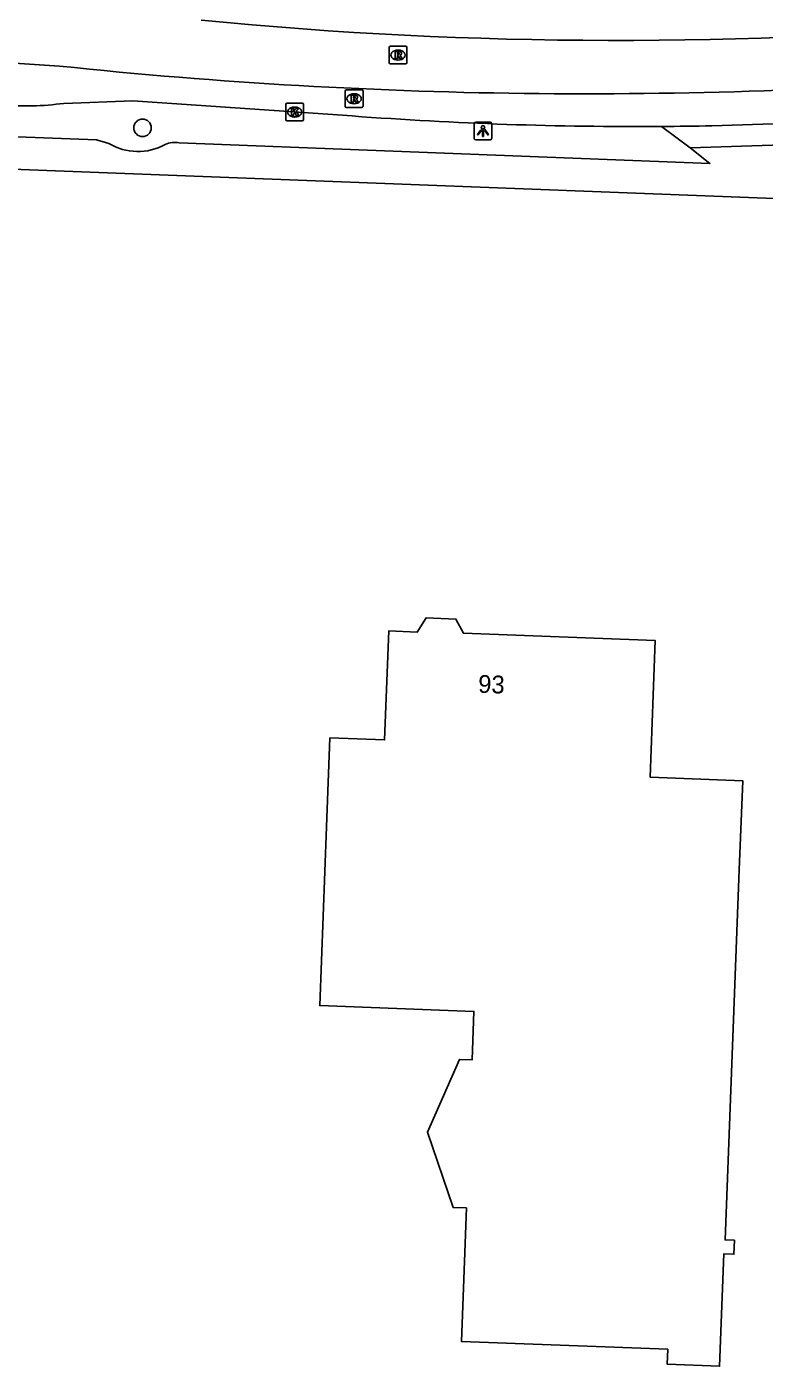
# Model space of a CAD drawing. Extents: x 161772 to 163123, y 383092 to 383917.
# Drawn here: x 162162.8 to 162204.2, y 383545.7 to 383620.9 of the extents above; entities that cross this region are included whole.
import ezdxf

# ---------------------------------------------------------------- set-up
doc = ezdxf.new("R2010")
doc.units = 0
for name, color, linetype in [('IMGEO_Boom', 7, 'Continuous'), ('IMGEO_Kolk', 7, 'Continuous'), ('IMGEO_Lichtpunt', 7, 'Continuous'), ('IMGEO_Pand', 7, 'Continuous'), ('IMGEO_Pand_nummerreeks', 7, 'Continuous'), ('IMGEO_Rijbaan_lokaal_gesloten', 7, 'Continuous'), ('IMGEO_Rioolput', 7, 'Continuous'), ('IMGEO_Voetpad_open', 7, 'Continuous')]:
    doc.layers.add(name, color=color, linetype=linetype)

msp = doc.modelspace()

# ---------------------------------------------------------------- linework, layer by layer
at = {"layer": 'IMGEO_Boom'}
msp.add_circle((162169.309, 383615.222), 0.489, dxfattribs=at)
at = {"layer": 'IMGEO_Kolk'}
for p, q in [((162177.353, 383615.684), (162177.353, 383616.536)), ((162177.428, 383616.61), (162178.28, 383616.61)), ((162177.841, 383616.39), (162177.866, 383616.39)), ((162178.354, 383616.536), (162178.354, 383615.684)), ((162178.28, 383615.61), (162177.428, 383615.61)), ((162177.864, 383615.83), (162177.839, 383615.83))]:
    msp.add_line(p, q, dxfattribs=at)
for points in [[(162177.353, 383615.684), (162177.353, 383616.536)], [(162177.428, 383616.61), (162178.28, 383616.61)], [(162177.674, 383616.31), (162177.797, 383616.31), (162177.797, 383616.159), (162177.927, 383616.31), (162178.091, 383616.31), (162177.945, 383616.159), (162178.098, 383615.91), (162177.946, 383615.91), (162177.861, 383616.074), (162177.797, 383616.007), (162177.797, 383615.91), (162177.674, 383615.91), (162177.674, 383616.31)], [(162178.354, 383616.536), (162178.354, 383615.684)], [(162178.28, 383615.61), (162177.428, 383615.61)]]:
    msp.add_lwpolyline(points, dxfattribs=at)
for centre, start, end in [((162177.43, 383616.534), 91.55205, 178.44795), ((162177.43, 383616.534), 91.55205, 178.44795), ((162178.278, 383616.534), 1.55205, 88.44795), ((162178.278, 383616.534), 1.55205, 88.44795), ((162177.43, 383615.686), 181.55205, 268.44795), ((162177.43, 383615.686), 181.55205, 268.44795), ((162178.278, 383615.686), 271.55205, 358.44795), ((162178.278, 383615.686), 271.55205, 358.44795)]:
    msp.add_arc(centre, 0.0765, start, end, dxfattribs=at)
for centre, major_axis, ratio, start_param, end_param in [((162177.84, 383616.11), (-0.387, 0.002), 0.722429, 4.712389, 7.853982), ((162177.865, 383616.11), (-0.39, 0.002), 0.717154, 1.570796, 4.712389)]:
    msp.add_ellipse(centre, major_axis=major_axis, ratio=ratio, start_param=start_param, end_param=end_param, dxfattribs=at)
at = {"layer": 'IMGEO_Lichtpunt'}
for p, q in [((162187.933, 383615.449), (162187.933, 383614.642)), ((162187.933, 383615.449), (162187.933, 383614.642)), ((162188.835, 383615.544), (162188.027, 383615.544)), ((162188.835, 383615.544), (162188.027, 383615.544)), ((162188.929, 383614.642), (162188.929, 383615.449)), ((162188.929, 383614.642), (162188.929, 383615.449)), ((162188.027, 383614.548), (162188.835, 383614.548)), ((162188.027, 383614.548), (162188.835, 383614.548))]:
    msp.add_line(p, q, dxfattribs=at)
for points in [[(162188.307, 383615.113), (162188.346, 383615.085), (162188.158, 383614.823), (162188.12, 383614.85), (162188.307, 383615.113)], [(162188.409, 383615.065), (162188.456, 383615.065), (162188.456, 383614.743), (162188.409, 383614.743), (162188.409, 383615.065)], [(162188.519, 383615.085), (162188.557, 383615.112), (162188.744, 383614.85), (162188.705, 383614.822), (162188.519, 383615.085)]]:
    msp.add_lwpolyline(points, dxfattribs=at)
msp.add_circle((162188.432, 383615.247), 0.0994, dxfattribs=at)
for centre, start, end in [((162188.027, 383615.449), 90, 180), ((162188.027, 383615.449), 90, 180), ((162188.835, 383615.449), 0, 90), ((162188.835, 383615.449), 0, 90), ((162188.027, 383614.642), 180, 270), ((162188.027, 383614.642), 180, 270), ((162188.835, 383614.642), 270, 0), ((162188.835, 383614.642), 270, 360)]:
    msp.add_arc(centre, 0.0946, start, end, dxfattribs=at)
at = {"layer": 'IMGEO_Pand'}
msp.add_lwpolyline([(162202.831, 383573.564), (162203.022, 383578.56), (162197.817, 383578.759), (162198.111, 383586.426), (162187.332, 383586.839), (162186.911, 383587.638), (162185.238, 383587.702), (162184.738, 383586.907), (162183.142, 383586.968), (162182.907, 383580.848), (162179.835, 383580.965), (162179.644, 383575.969), (162179.26, 383565.936), (162187.929, 383565.604), (162187.825, 383562.883), (162187.106, 383562.91), (162185.309, 383558.829), (162186.765, 383554.596), (162187.506, 383554.567), (162187.219, 383547.073), (162198.814, 383546.629), (162198.782, 383545.794), (162201.728, 383545.681), (162201.969, 383551.993), (162202.528, 383551.972), (162202.558, 383552.752), (162202.034, 383552.772), (162202.831, 383573.564)], dxfattribs=at)
at = {"layer": 'IMGEO_Rijbaan_lokaal_gesloten'}
for points in [[(162161.548, 383618.884), (162164.644, 383618.69)], [(162181.085, 383615.888), (162168.773, 383616.735), (162164.893, 383616.595)], [(162212.842, 383615.851), (162207.025, 383615.525), (162201.283, 383615.334)]]:
    msp.add_lwpolyline(points, dxfattribs=at)
for centre, radius, start, end in [((162196.013, 383862.02), 241.892, 264.44839, 275.296), ((162194.259, 383899.063), 281.932, 263.9704, 274.94108), ((162162.72, 383632.69), 16.241, 265.15652, 277.68828), ((162197.055, 383829.7), 214.407, 265.72839, 270.37491), ((162196.971, 383836.713), 221.421, 270.38484, 271.11592)]:
    msp.add_arc(centre, radius, start, end, dxfattribs=at)
at = {"layer": 'IMGEO_Rioolput'}
for p, q in [((162183.237, 383619.807), (162184.089, 383619.807)), ((162183.162, 383618.881), (162183.162, 383619.733)), ((162183.65, 383619.587), (162183.675, 383619.587)), ((162184.163, 383619.733), (162184.163, 383618.881)), ((162184.089, 383618.807), (162183.237, 383618.807)), ((162183.673, 383619.027), (162183.648, 383619.027)), ((162180.693, 383616.429), (162180.693, 383617.281)), ((162180.768, 383617.355), (162181.62, 383617.355)), ((162181.181, 383617.135), (162181.206, 383617.135)), ((162181.694, 383617.281), (162181.694, 383616.429)), ((162181.62, 383616.355), (162180.768, 383616.355)), ((162181.204, 383616.575), (162181.179, 383616.575))]:
    msp.add_line(p, q, dxfattribs=at)
for points in [[(162183.237, 383619.807), (162184.089, 383619.807)], [(162183.162, 383618.881), (162183.162, 383619.733)], [(162183.751, 383619.505), (162183.499, 383619.507), (162183.499, 383619.107)], [(162183.499, 383619.107), (162183.623, 383619.107), (162183.623, 383619.269), (162183.634, 383619.269)], [(162183.677, 383619.426), (162183.623, 383619.426), (162183.623, 383619.345)], [(162183.623, 383619.345), (162183.675, 383619.345)], [(162183.681, 383619.24), (162183.752, 383619.107), (162183.892, 383619.107), (162183.827, 383619.233)], [(162184.163, 383619.733), (162184.163, 383618.881)], [(162184.089, 383618.807), (162183.237, 383618.807)], [(162180.693, 383616.429), (162180.693, 383617.281)], [(162180.768, 383617.355), (162181.62, 383617.355)], [(162181.282, 383617.053), (162181.03, 383617.055), (162181.03, 383616.655)], [(162181.03, 383616.655), (162181.154, 383616.655), (162181.154, 383616.817), (162181.165, 383616.817)], [(162181.208, 383616.974), (162181.154, 383616.974), (162181.154, 383616.893)], [(162181.154, 383616.893), (162181.206, 383616.893)], [(162181.694, 383617.281), (162181.694, 383616.429)], [(162181.62, 383616.355), (162180.768, 383616.355)], [(162181.212, 383616.788), (162181.283, 383616.655), (162181.423, 383616.655), (162181.358, 383616.781)]]:
    msp.add_lwpolyline(points, dxfattribs=at)
for centre, radius, start, end in [((162183.239, 383619.731), 0.0765, 91.55205, 178.44795), ((162183.239, 383619.731), 0.0765, 91.55205, 178.44795), ((162184.087, 383619.731), 0.0765, 1.55205, 88.44795), ((162184.087, 383619.731), 0.0765, 1.55205, 88.44795), ((162183.633, 383619.216), 0.0533, 26.02933, 88.69889), ((162183.659, 383619.534), 0.19, 274.7715, 282.96867), ((162183.683, 383619.33), 0.0964, 77.00612, 93.18647), ((162183.697, 383619.387), 0.0378, 276.66336, 79.67722), ((162183.75, 383619.395), 0.109, 350.36119, 89.41601), ((162183.748, 383619.395), 0.112, 277.58423, 350.98172), ((162183.732, 383619.18), 0.108, 29.51342, 73.79051), ((162183.239, 383618.883), 0.0765, 181.55205, 268.44795), ((162183.239, 383618.883), 0.0765, 181.55205, 268.44795), ((162184.087, 383618.883), 0.0765, 271.55205, 358.44795), ((162184.087, 383618.883), 0.0765, 271.55205, 358.44795), ((162180.77, 383617.279), 0.0765, 91.55205, 178.44795), ((162180.77, 383617.279), 0.0765, 91.55205, 178.44795), ((162181.164, 383616.764), 0.0533, 26.02933, 88.69889), ((162181.19, 383617.082), 0.19, 274.7715, 282.96867), ((162181.214, 383616.878), 0.0964, 77.00612, 93.18647), ((162181.228, 383616.935), 0.0378, 276.66336, 79.67722), ((162181.281, 383616.943), 0.109, 350.36119, 89.41601), ((162181.279, 383616.943), 0.112, 277.58423, 350.98172), ((162181.263, 383616.728), 0.108, 29.51342, 73.79051), ((162181.618, 383617.279), 0.0765, 1.55205, 88.44795), ((162181.618, 383617.279), 0.0765, 1.55205, 88.44795), ((162180.77, 383616.431), 0.0765, 181.55205, 268.44795), ((162180.77, 383616.431), 0.0765, 181.55205, 268.44795), ((162181.618, 383616.431), 0.0765, 271.55205, 358.44795), ((162181.618, 383616.431), 0.0765, 271.55205, 358.44795)]:
    msp.add_arc(centre, radius, start, end, dxfattribs=at)
for centre, major_axis, ratio, start_param, end_param in [((162183.649, 383619.307), (-0.387, 0.002), 0.722429, 4.712389, 7.853982), ((162183.674, 383619.307), (-0.39, 0.002), 0.717154, 1.570796, 4.712389), ((162181.18, 383616.855), (-0.387, 0.002), 0.722429, 4.712389, 7.853982), ((162181.205, 383616.855), (-0.39, 0.002), 0.717154, 1.570796, 4.712389)]:
    msp.add_ellipse(centre, major_axis=major_axis, ratio=ratio, start_param=start_param, end_param=end_param, dxfattribs=at)
at = {"layer": 'IMGEO_Voetpad_open'}
for points in [[(162147.874, 383613.435), (162207.733, 383611.15), (162209.591, 383611.164), (162215.124, 383611.45), (162220.638, 383611.986), (162235.499, 383613.996), (162256.802, 383617.115)], [(162167.41, 383614.341), (162166.716, 383614.546), (162147.96, 383615.264), (162148.006, 383616.868)], [(162198.458, 383615.297), (162200.066, 383614.093)], [(162212.917, 383614.656), (162207, 383614.324), (162201.227, 383614.132), (162200.066, 383614.093)], [(162200.066, 383614.093), (162201.184, 383613.223), (162171.369, 383614.377)]]:
    msp.add_lwpolyline(points, dxfattribs=at)
for centre, radius, start, end in [((162169.05, 383617.115), 3.223, 239.40572, 298.31649), ((162171.108, 383613.257), 1.15, 76.89783, 117.3879)]:
    msp.add_arc(centre, radius, start, end, dxfattribs=at)

# ---------------------------------------------------------------- texts
at = {"layer": 'IMGEO_Pand_nummerreeks'}
msp.add_text('93', height=1, rotation=357.93162, dxfattribs=at).set_placement((162188.149, 383583.503))

doc.saveas('drawing.dxf')
